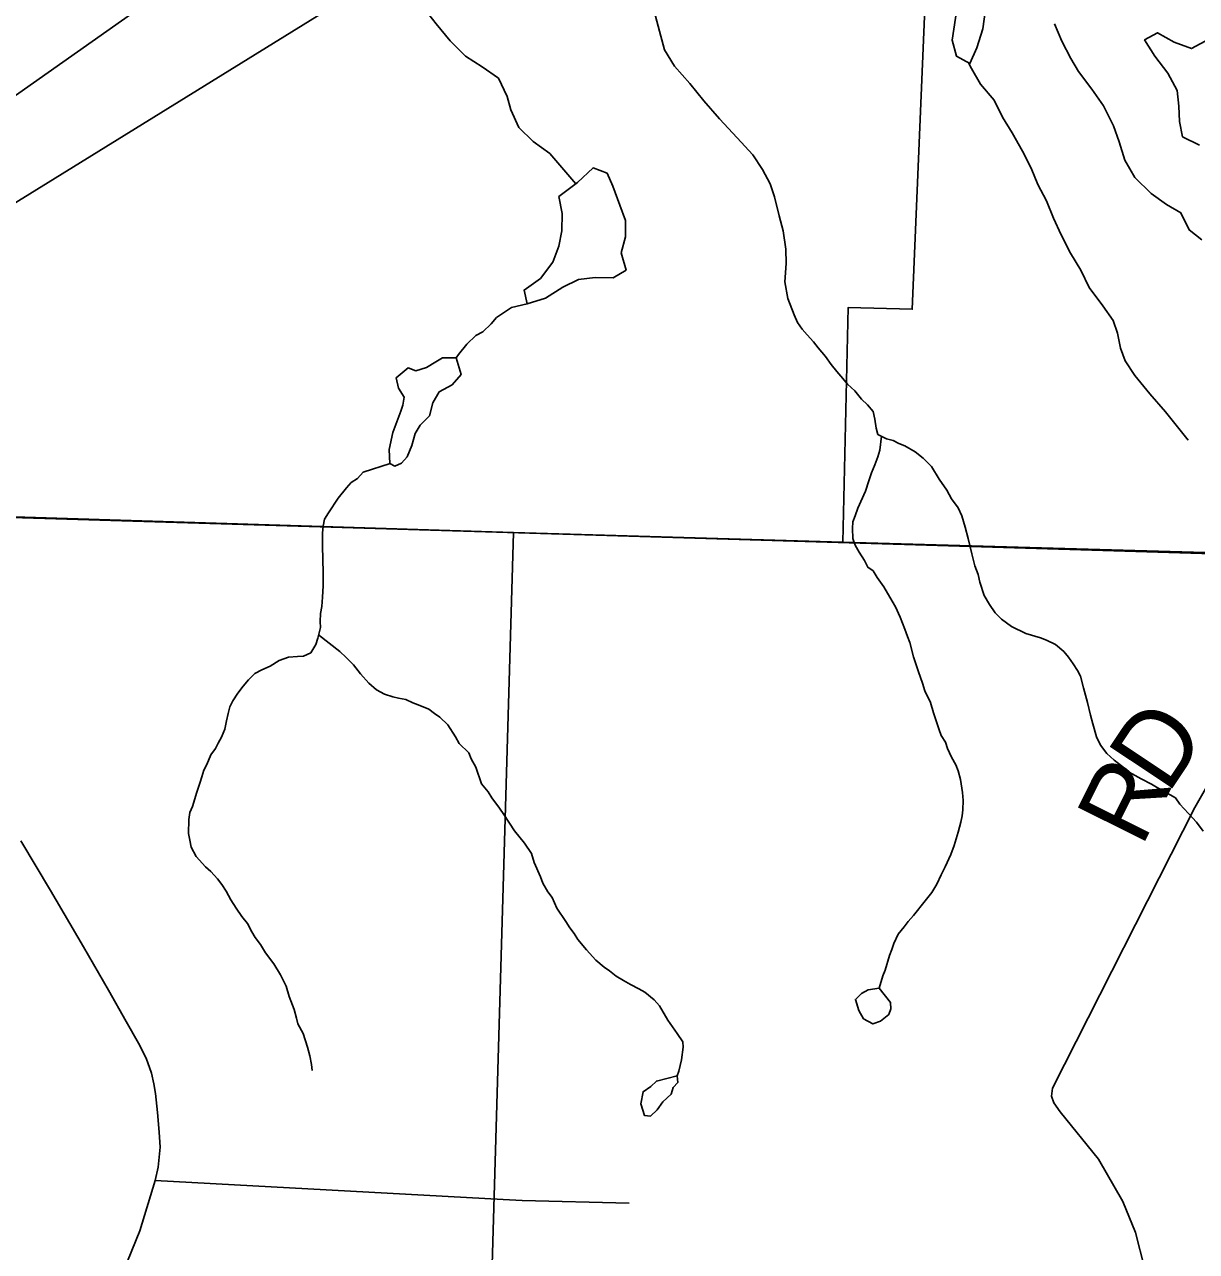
# Model space of a CAD drawing. Extents: x -7.5 to 26.5, y 3.5 to 25.5.
# Drawn here: x -1.65 to -0.763, y 20.587 to 21.515 of the extents above; entities that cross this region are included whole.
import ezdxf

# ---------------------------------------------------------------- set-up
doc = ezdxf.new("R2010")
doc.units = 0
for name, color, linetype in [('GM_X_Corporation', 7, 'Continuous'), ('GM_X_County_Road', 7, 'Continuous'), ('GM_X_County_Road_Text', 7, 'Continuous'), ('GM_X_Major_Lake', 7, 'Continuous'), ('GM_X_Minor_River', 7, 'Continuous'), ('GM_X_Township_Road', 7, 'Continuous'), ('SH_Text', 7, 'Continuous')]:
    doc.layers.add(name, color=color, linetype=linetype)

msp = doc.modelspace()

# ---------------------------------------------------------------- linework, layer by layer
at = {"layer": 'GM_X_Corporation'}
for points in [[(-2.12132, 24.4), (-2.16833, 23.10943), (-2.16844, 23.10644), (-2.1854, 22.64074), (-2.20479, 22.10845), (-2.22181, 21.64119), (-2.23926, 21.16218), (-1.70129, 21.14354), (-0.66731, 21.11233), (-0.27514, 21.10045), (-0.19179, 21.09715), (-0.18643, 21.09714), (-0.18063, 21.09671), (-0.08571, 21.09295), (-0.04384, 21.09129), (0.07287, 21.08754), (0.22111, 21.08276)], [(0.22111, 21.08276), (0.07287, 21.08754), (-0.04384, 21.09129), (-0.08571, 21.09295), (-0.18063, 21.09671), (-0.18643, 21.09714), (-0.19179, 21.09715), (-0.27514, 21.10045), (-0.66731, 21.11233), (-1.70129, 21.14354), (-2.23926, 21.16218), (-2.26433, 20.45719), (-2.26496, 20.43952), (-2.27282, 20.24956), (-2.31277, 19.1642), (-2.34011, 19.1651), (-2.69299, 19.17676), (-2.69597, 19.17682), (-3.31657, 19.18955)]]:
    msp.add_lwpolyline(points, dxfattribs=at)
for points in [[(-2.24786, 22.12167), (-0.94612, 22.06009), (-0.97818, 21.29975), (-1.02673, 21.30097), (-1.03065, 21.12371), (-1.27976, 21.1309), (-2.268, 21.16183)], [(-0.94612, 22.06009), (-0.1108, 22.04288), (-0.27046, 21.10184), (-1.03065, 21.12371), (-1.02673, 21.30097), (-0.97818, 21.29975)], [(-2.268, 21.16183), (-1.27976, 21.1309), (-1.30885, 20.13598), (-2.29478, 20.16306)], [(-1.27976, 21.1309), (-1.03065, 21.12371), (-0.27046, 21.10184), (-0.30817, 20.12646), (-1.30885, 20.13598)]]:
    msp.add_lwpolyline(points, close=True, dxfattribs=at)
at = {"layer": 'GM_X_County_Road'}
for points in [[(-0.82172, 19.71076), (-0.80187, 20.28795), (-0.79643, 20.52942), (-0.79736, 20.5511), (-0.80241, 20.57479), (-0.80927, 20.60157), (-0.81888, 20.625), (-0.83737, 20.65702), (-0.86638, 20.69273), (-0.87112, 20.6997), (-0.87289, 20.70468), (-0.87196, 20.71074), (-0.76446, 20.92292), (-0.7533, 20.94237), (-0.73718, 20.96285), (-0.72491, 20.98114), (-0.71699, 20.99308), (-0.7065, 21.01598), (-0.68896, 21.06766)], [(-1.65243, 20.89782), (-1.63, 20.86011), (-1.60496, 20.81768), (-1.58594, 20.78468), (-1.57261, 20.76111), (-1.56335, 20.74469), (-1.55749, 20.73331), (-1.55359, 20.72209), (-1.55164, 20.71396), (-1.5505, 20.70665), (-1.54888, 20.69234), (-1.54774, 20.67739), (-1.54693, 20.66617), (-1.54855, 20.65089), (-1.55067, 20.64081), (-1.56245, 20.60273), (-1.60122, 20.50725)]]:
    msp.add_lwpolyline(points, dxfattribs=at)
at = {"layer": 'GM_X_Major_Lake'}
for points in [[(-0.94424, 21.52829), (-0.94785, 21.50327), (-0.94471, 21.49103), (-0.93458, 21.48548), (-0.92937, 21.49753), (-0.92487, 21.51188), (-0.92306, 21.52477)], [(-0.87048, 21.5156), (-0.86508, 21.50255), (-0.85817, 21.48946), (-0.85232, 21.47944), (-0.84236, 21.46629), (-0.83354, 21.45354), (-0.8259, 21.43854), (-0.82163, 21.42628), (-0.81738, 21.41249), (-0.8097, 21.39939), (-0.79745, 21.38732), (-0.78586, 21.37908), (-0.77499, 21.37274), (-0.76883, 21.35968), (-0.75913, 21.35223)], [(-0.76093, 21.42376), (-0.77369, 21.43013), (-0.77609, 21.4416), (-0.77658, 21.4534), (-0.77783, 21.46521), (-0.78475, 21.4783), (-0.79472, 21.49107), (-0.80241, 21.50341), (-0.79279, 21.5089), (-0.78004, 21.50177), (-0.76686, 21.4969), (-0.75341, 21.50421)]]:
    msp.add_lwpolyline(points, dxfattribs=at)
at = {"layer": 'GM_X_Minor_River'}
for p, q in [((-1.28121, 21.30112), (-1.26935, 21.30388)), ((-1.33348, 21.26299), (-1.32313, 21.26287)), ((-0.99455, 20.77556), (-1.00314, 20.78631)), ((-1.15538, 20.71484), (-1.15602, 20.71988))]:
    msp.add_line(p, q, dxfattribs=at)
for points in [[(-1.46855, 21.59494), (-1.46161, 21.59081), (-1.44988, 21.5886), (-1.43741, 21.58637), (-1.42414, 21.58526), (-1.41432, 21.5831), (-1.40147, 21.58048), (-1.38944, 21.5756), (-1.37791, 21.56617), (-1.36643, 21.55483), (-1.35802, 21.54244), (-1.34924, 21.52965), (-1.33821, 21.51567), (-1.32753, 21.50284), (-1.31607, 21.49112), (-1.30336, 21.48318), (-1.29105, 21.47449), (-1.28458, 21.46062), (-1.2818, 21.45066), (-1.2757, 21.43718), (-1.26496, 21.42663), (-1.25228, 21.41755), (-1.2327, 21.39458)], [(-1.06741, 21.29548), (-1.07227, 21.30797), (-1.07464, 21.32057), (-1.07357, 21.33424), (-1.0737, 21.34527), (-1.07567, 21.359), (-1.07883, 21.37048), (-1.0823, 21.38463), (-1.0855, 21.39459), (-1.09133, 21.40537), (-1.09867, 21.41656), (-1.11053, 21.42938), (-1.12387, 21.44375), (-1.13572, 21.45732), (-1.14643, 21.47049), (-1.1579, 21.48368), (-1.1656, 21.49602), (-1.17499, 21.53181)], [(-0.93569, 21.48609), (-0.93334, 21.48181), (-0.92644, 21.46984), (-0.91612, 21.45778), (-0.90999, 21.44506), (-0.90271, 21.43308), (-0.89472, 21.41917), (-0.88822, 21.40645), (-0.88323, 21.39415), (-0.87671, 21.3818), (-0.87136, 21.36873), (-0.86562, 21.35602), (-0.85839, 21.34214), (-0.85074, 21.32938), (-0.84425, 21.31628), (-0.83398, 21.30232)], [(-1.24554, 21.38504), (-1.23121, 21.39569), (-1.21952, 21.4068), (-1.20898, 21.40271), (-1.20469, 21.39271), (-1.19937, 21.3785), (-1.19511, 21.36697), (-1.19506, 21.35442), (-1.19842, 21.34233), (-1.19459, 21.3293), (-1.20424, 21.32347), (-1.21791, 21.32383), (-1.23049, 21.32225), (-1.24242, 21.31648), (-1.25556, 21.30808), (-1.26935, 21.30388)], [(-1.26935, 21.30388), (-1.27173, 21.31421), (-1.25934, 21.32301), (-1.2499, 21.33532), (-1.2454, 21.34737), (-1.24319, 21.35911), (-1.24285, 21.37203), (-1.24554, 21.38504)], [(-1.28121, 21.30112), (-1.28718, 21.29702), (-1.29262, 21.29341), (-1.29658, 21.2886), (-1.30286, 21.28274), (-1.30827, 21.27989), (-1.31496, 21.27328), (-1.3213, 21.26552), (-1.32313, 21.26287)], [(-1.06741, 21.29548), (-1.06495, 21.2897), (-1.06133, 21.28463), (-1.05768, 21.28032), (-1.05293, 21.27522), (-1.04929, 21.27053), (-1.04382, 21.26388), (-1.03947, 21.25803), (-1.0351, 21.25256), (-1.03073, 21.24747), (-1.02708, 21.24316), (-1.02156, 21.23803), (-1.01646, 21.23177), (-1.01206, 21.22744), (-1.00768, 21.22235), (-1.00635, 21.2166), (-1.00545, 21.20973), (-1.00409, 21.20512), (-0.99775, 21.20186), (-0.99248, 21.20054), (-0.98839, 21.19811), (-0.98389, 21.19644), (-0.97607, 21.19199), (-0.96979, 21.18721), (-0.96355, 21.18091), (-0.95781, 21.17121), (-0.95202, 21.16303), (-0.94845, 21.15645), (-0.94338, 21.14943), (-0.94054, 21.14363), (-0.93819, 21.13481), (-0.93582, 21.12636), (-0.93318, 21.11487), (-0.93084, 21.10567), (-0.92841, 21.09912), (-0.92709, 21.09338), (-0.92364, 21.08338), (-0.91971, 21.0764), (-0.91537, 21.07017), (-0.91059, 21.06544), (-0.90319, 21.05987), (-0.89237, 21.05455), (-0.88109, 21.05112), (-0.8766, 21.04944), (-0.86988, 21.04617), (-0.8636, 21.04101), (-0.85995, 21.03671), (-0.85633, 21.03164), (-0.85309, 21.02659), (-0.85096, 21.02233), (-0.84861, 21.01351), (-0.84557, 21.00238), (-0.84325, 20.9928), (-0.84158, 20.98628), (-0.83888, 20.97631), (-0.83568, 20.97012), (-0.83096, 20.96387), (-0.82544, 20.95874), (-0.81879, 20.95357), (-0.81399, 20.9496), (-0.80505, 20.94473), (-0.79721, 20.94066), (-0.78903, 20.93582), (-0.78307, 20.93257), (-0.77898, 20.93015), (-0.77572, 20.92547), (-0.76913, 20.9184), (-0.76329, 20.91174), (-0.7582, 20.9051)], [(-0.83398, 21.30232), (-0.82613, 21.29128), (-0.82299, 21.28169), (-0.82066, 21.27022), (-0.81714, 21.26061), (-0.80986, 21.24976), (-0.79849, 21.23575), (-0.78673, 21.22211), (-0.77756, 21.21082), (-0.7695, 21.20071)], [(-1.32313, 21.26287), (-1.31937, 21.25046), (-1.32604, 21.24265), (-1.33606, 21.23721), (-1.34084, 21.22898), (-1.34338, 21.21917), (-1.35041, 21.21213), (-1.354, 21.20577), (-1.35652, 21.19672), (-1.36017, 21.18807), (-1.36448, 21.18325), (-1.36947, 21.1811), (-1.37322, 21.1831), (-1.3737, 21.19375), (-1.37108, 21.2066), (-1.36495, 21.22278), (-1.36331, 21.2273), (-1.36238, 21.23335), (-1.36677, 21.23993), (-1.36846, 21.24796), (-1.35952, 21.25532), (-1.3535, 21.25326), (-1.34545, 21.25571), (-1.3385, 21.26008), (-1.33348, 21.26299)], [(-1.00149, 21.20378), (-1.0026, 21.19329), (-1.00431, 21.18803), (-1.00641, 21.18202), (-1.0089, 21.17602), (-1.011, 21.17001), (-1.01355, 21.16212), (-1.01931, 21.1494), (-1.02142, 21.14339), (-1.02309, 21.13889), (-1.02326, 21.13396), (-1.02314, 21.12635), (-1.02142, 21.12135), (-1.01819, 21.11592), (-1.01423, 21.1097), (-1.01174, 21.10467), (-1.00766, 21.10187), (-1.0048, 21.09683), (-0.99973, 21.08981), (-0.99506, 21.08205), (-0.99076, 21.07468), (-0.98723, 21.06696), (-0.98376, 21.05772), (-0.98166, 21.05232), (-0.97992, 21.0477), (-0.97726, 21.03697), (-0.97348, 21.02544), (-0.97036, 21.01697), (-0.96866, 21.01121), (-0.96441, 21.00232), (-0.96202, 20.99464), (-0.95791, 20.98157), (-0.95616, 20.97733), (-0.95292, 20.97228), (-0.95156, 20.96767), (-0.94837, 20.9611), (-0.94516, 20.95529), (-0.94342, 20.95067), (-0.94174, 20.94415), (-0.94019, 20.93421), (-0.93964, 20.92811), (-0.93988, 20.92128), (-0.94041, 20.91674), (-0.94134, 20.91183), (-0.9435, 20.9043), (-0.94651, 20.89415), (-0.94902, 20.88739), (-0.95314, 20.87803), (-0.95639, 20.87206), (-0.95967, 20.86496), (-0.96331, 20.85863), (-0.96846, 20.85234), (-0.9772, 20.84124), (-0.98115, 20.83682), (-0.98432, 20.83275), (-0.98869, 20.8272), (-0.99198, 20.82009), (-0.99365, 20.81559), (-0.99532, 20.81109), (-0.99875, 20.79981), (-1.00041, 20.79568), (-1.00314, 20.78631)], [(-1.37295, 21.18296), (-1.39348, 21.17643), (-1.39782, 21.17164), (-1.40248, 21.16876), (-1.40604, 21.1647), (-1.41238, 21.15694), (-1.4196, 21.14579), (-1.4228, 21.14096), (-1.42374, 21.13567), (-1.42431, 21.13037), (-1.42408, 21.1258), (-1.42426, 21.12087), (-1.42385, 21.11059), (-1.42381, 21.10071), (-1.42379, 21.09045), (-1.42408, 21.0821), (-1.42471, 21.0749), (-1.42565, 21.06961), (-1.42586, 21.06353), (-1.42564, 21.05897), (-1.42781, 21.05106), (-1.42912, 21.04617), (-1.43313, 21.03985), (-1.43853, 21.03737), (-1.4431, 21.03715), (-1.44995, 21.03663), (-1.45687, 21.03421), (-1.46385, 21.02989), (-1.47002, 21.02706), (-1.47544, 21.02421), (-1.48016, 21.01943), (-1.48412, 21.01463), (-1.4881, 21.00945), (-1.4921, 21.0035), (-1.49415, 20.99902), (-1.49546, 20.99412), (-1.49679, 20.98847), (-1.49816, 20.98205), (-1.50064, 20.97606), (-1.50307, 20.97158), (-1.50511, 20.96747), (-1.5087, 20.96265), (-1.5116, 20.95553), (-1.51403, 20.95106), (-1.51534, 20.94616), (-1.51662, 20.94203), (-1.51916, 20.93451), (-1.52258, 20.92361), (-1.52463, 20.91912), (-1.52519, 20.91382), (-1.52556, 20.90319), (-1.52459, 20.89822), (-1.52364, 20.89286), (-1.5197, 20.88589), (-1.51276, 20.87805), (-1.50871, 20.87448), (-1.50358, 20.86899), (-1.50032, 20.86469), (-1.49707, 20.85964), (-1.4935, 20.85306), (-1.48954, 20.84684), (-1.4852, 20.84061), (-1.48084, 20.83513), (-1.47763, 20.82894), (-1.47512, 20.82467), (-1.47114, 20.81922), (-1.46718, 20.813), (-1.461, 20.8048), (-1.45598, 20.79627), (-1.45172, 20.78776), (-1.44933, 20.78007), (-1.4455, 20.77006), (-1.44383, 20.76354), (-1.44284, 20.75933), (-1.43891, 20.75197), (-1.43548, 20.74159), (-1.4338, 20.73507), (-1.43251, 20.72857), (-1.43191, 20.72398)], [(-1.42715, 21.05345), (-1.41107, 21.04098), (-1.4063, 21.03625), (-1.4008, 21.03074), (-1.39533, 21.02409), (-1.38912, 21.01704), (-1.38323, 21.01189), (-1.37726, 21.00865), (-1.37088, 21.00652), (-1.36673, 21.00562), (-1.36108, 21.00466), (-1.35584, 21.0022), (-1.35173, 21.00054), (-1.34387, 20.99723), (-1.33942, 20.99403), (-1.33534, 20.99123), (-1.32947, 20.98533), (-1.32371, 20.97639), (-1.32084, 20.97135), (-1.3135, 20.96425), (-1.31176, 20.95963), (-1.30818, 20.95342), (-1.30406, 20.94074), (-1.29895, 20.93486), (-1.29607, 20.9302), (-1.29027, 20.9224), (-1.28701, 20.91773), (-1.27909, 20.90529), (-1.27144, 20.89591), (-1.26602, 20.88812), (-1.26398, 20.88121), (-1.25941, 20.8704), (-1.25767, 20.86578), (-1.25373, 20.85919), (-1.25046, 20.85489), (-1.24694, 20.84679), (-1.24008, 20.83667), (-1.2372, 20.83201), (-1.23393, 20.82772), (-1.23106, 20.82306), (-1.22449, 20.81523), (-1.21755, 20.80739), (-1.21128, 20.80223), (-1.2072, 20.79943), (-1.20202, 20.79545), (-1.19644, 20.79221), (-1.19123, 20.78899), (-1.18489, 20.78573), (-1.18042, 20.7833), (-1.17341, 20.77735), (-1.16938, 20.77303), (-1.16293, 20.76217), (-1.15606, 20.75205), (-1.15172, 20.74582), (-1.15149, 20.74163), (-1.15257, 20.73217), (-1.15477, 20.7235), (-1.15602, 20.71988)], [(-1.00314, 20.78631), (-1.0114, 20.78513), (-1.01642, 20.78223), (-1.02109, 20.77779), (-1.01866, 20.76936), (-1.01502, 20.76319), (-1.00791, 20.7592), (-1.00215, 20.76133), (-0.99594, 20.76648), (-0.99431, 20.77062), (-0.99455, 20.77556)], [(-1.15602, 20.71988), (-1.17169, 20.71603), (-1.17597, 20.71197), (-1.18178, 20.70794), (-1.18354, 20.69887), (-1.18073, 20.69005), (-1.17619, 20.68955), (-1.17112, 20.69436), (-1.16678, 20.70032), (-1.16055, 20.70624), (-1.1589, 20.71114), (-1.15538, 20.71484)]]:
    msp.add_lwpolyline(points, dxfattribs=at)
at = {"layer": 'GM_X_Township_Road'}
msp.add_line((-1.55067, 20.64081), (-1.28766, 20.62637), dxfattribs=at)
msp.add_lwpolyline([(-1.28766, 20.62637), (-1.27323, 20.62561), (-1.19235, 20.62377)], dxfattribs=at)
at = {"layer": 'SH_Text'}
msp.add_lwpolyline([(2.44493, 24.35104), (-2.59609, 20.79948), (2.44493, 23.91629)], close=True, dxfattribs=at)

# ---------------------------------------------------------------- texts
at = {"layer": 'GM_X_County_Road_Text'}
for s, rotation, p in [('D', 56.34137, (-0.78491, 20.93222)), ('R', 63.51785, (-0.80478, 20.89207))]:
    msp.add_text(s, height=0.05682, rotation=rotation, dxfattribs=at).set_placement(p)

doc.saveas('drawing.dxf')
